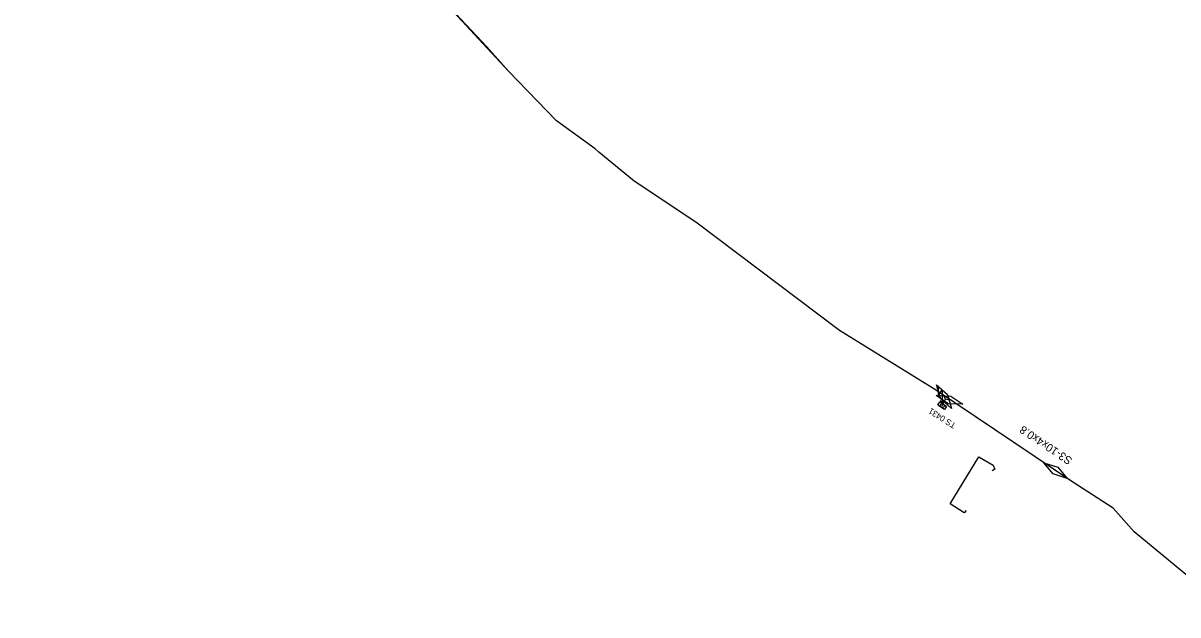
# Model space of a CAD drawing. Extents: x -748507 to -687366, y -1057342 to -1024924.
# Drawn here: x -745936 to -745647.3, y -1029106.6 to -1028958.7 of the extents above; entities that cross this region are included whole.
import ezdxf

# ---------------------------------------------------------------- set-up
doc = ezdxf.new("R2010")
doc.units = 0
for name, color, linetype in [('6kV - SŽDC', 7, 'Continuous'), ('DK + TKK - SŽDC', 7, 'Continuous'), ('TK+DOK_Pha Holešovice - Kralupy', 7, 'Continuous'), ('Vedení NN - SŽDC', 7, 'Continuous')]:
    doc.layers.add(name, color=color, linetype=linetype)

msp = doc.modelspace()

# ---------------------------------------------------------------- linework, layer by layer
at = {"layer": '6kV - SŽDC'}
for p, q in [((-745707.25, -1029049.33), (-745707.25, -1029051.83)), ((-745707.25, -1029051.83), (-745706.25, -1029050.33)), ((-745706.25, -1029050.33), (-745706.25, -1029053.83)), ((-745706.75, -1029052.93), (-745706.25, -1029053.83)), ((-745706.3, -1029054.33), (-745706.2, -1029054.33)), ((-745706.25, -1029053.83), (-745705.75, -1029052.93))]:
    msp.add_line(p, q, dxfattribs=at)
for points in [[(-745703.89, -1029055.02), (-745706.6, -1029052.6), (-745707.64, -1029049.1), (-745704.92, -1029051.52), (-745703.89, -1029055.02)], [(-745707.77, -1029051.82), (-745704.13, -1029051.95), (-745701.11, -1029053.98), (-745704.75, -1029053.85), (-745707.77, -1029051.82)], [(-745706.25, -1029054.33), (-745705.43, -1029052.58), (-745705.76, -1029052.06)], [(-745705.14, -1029054.44), (-745705.67, -1029055.29), (-745707.36, -1029054.22), (-745706.83, -1029053.37), (-745705.14, -1029054.44)], [(-745705.43, -1029052.58), (-745704.44, -1029052.9)]]:
    msp.add_lwpolyline(points, dxfattribs=at)
msp.add_circle((-745706.25, -1029054.33), 0.5, dxfattribs=at)
at = {"layer": 'DK + TKK - SŽDC'}
for points in [[(-745658.29, -1029085.88), (-745663.5, -1029079.92), (-745673.62, -1029073.46), (-745707.69, -1029050.57), (-745731.95, -1029035.55), (-745767.83, -1029008.4), (-745783.26, -1028998.21), (-745792.09, -1028990.9), (-745792.94, -1028990.1), (-745802.66, -1028983.07), (-745814.67, -1028970.7), (-745820.03, -1028964.64), (-745836.92, -1028946.63)], [(-745630.8, -1029106.64), (-745644.42, -1029097.3), (-745658.29, -1029085.88), (-745663.5, -1029079.92), (-745673.62, -1029073.46), (-745707.69, -1029050.57), (-745731.95, -1029035.55), (-745767.83, -1029008.4), (-745783.26, -1028998.21), (-745792.09, -1028990.9), (-745792.94, -1028990.1), (-745802.66, -1028983.07), (-745814.67, -1028970.7)], [(-745644.42, -1029097.3), (-745658.29, -1029085.88)]]:
    msp.add_lwpolyline(points, dxfattribs=at)
at = {"layer": 'TK+DOK_Pha Holešovice - Kralupy'}
for points in [[(-745814.67, -1028970.7), (-745836.92, -1028946.63), (-745857.99, -1028916.28), (-745868.92, -1028899.57), (-745880.27, -1028879.29), (-745900.3, -1028837.87), (-745905.82, -1028823.63), (-745915.35, -1028795.84), (-745923.34, -1028768.36), (-745928.68, -1028742.13), (-745932.49, -1028716.53), (-745935.02, -1028689.29), (-745935.66, -1028678.96), (-745935.96, -1028664.21), (-745935.73, -1028649.61), (-745935.67, -1028634.8), (-745935.63, -1028631.69)], [(-745677.94, -1029070.56), (-745707.69, -1029050.57), (-745731.95, -1029035.55), (-745767.83, -1029008.4), (-745783.26, -1028998.21), (-745792.09, -1028990.9), (-745792.94, -1028990.1), (-745802.66, -1028983.07), (-745814.67, -1028970.7), (-745836.92, -1028946.63)], [(-745630.8, -1029106.64), (-745644.42, -1029097.3), (-745658.29, -1029085.88), (-745663.5, -1029079.92), (-745673.62, -1029073.46), (-745677.94, -1029070.56), (-745707.69, -1029050.57), (-745731.95, -1029035.55), (-745767.83, -1029008.4), (-745783.26, -1028998.21), (-745792.09, -1028990.9), (-745792.94, -1028990.1), (-745802.66, -1028983.07), (-745814.67, -1028970.7)], [(-745675.03, -1029072.51), (-745678.49, -1029071.39), (-745680.84, -1029068.61), (-745677.38, -1029069.73), (-745675.03, -1029072.51)], [(-745644.42, -1029097.3), (-745658.29, -1029085.88), (-745663.5, -1029079.92), (-745673.62, -1029073.46), (-745677.94, -1029070.56)]]:
    msp.add_lwpolyline(points, dxfattribs=at)
at = {"layer": 'Vedení NN - SŽDC'}
msp.add_lwpolyline([(-745700.22, -1029080.53), (-745700.74, -1029081.12), (-745704.22, -1029078.86), (-745697.13, -1029067.13), (-745693.5, -1029069.2), (-745693.11, -1029070.2), (-745693.77, -1029070.63)], dxfattribs=at)

# ---------------------------------------------------------------- texts
at = {"layer": '6kV - SŽDC'}
msp.add_text('TS 0431', height=1.5, rotation=147.7769, dxfattribs=at).set_placement((-745702.66, -1029058.85))
at = {"layer": 'TK+DOK_Pha Holešovice - Kralupy'}
msp.add_text('S3-10x4x0.8', height=2, rotation=146.105, dxfattribs=at).set_placement((-745673.57, -1029067.58))

doc.saveas('drawing.dxf')
